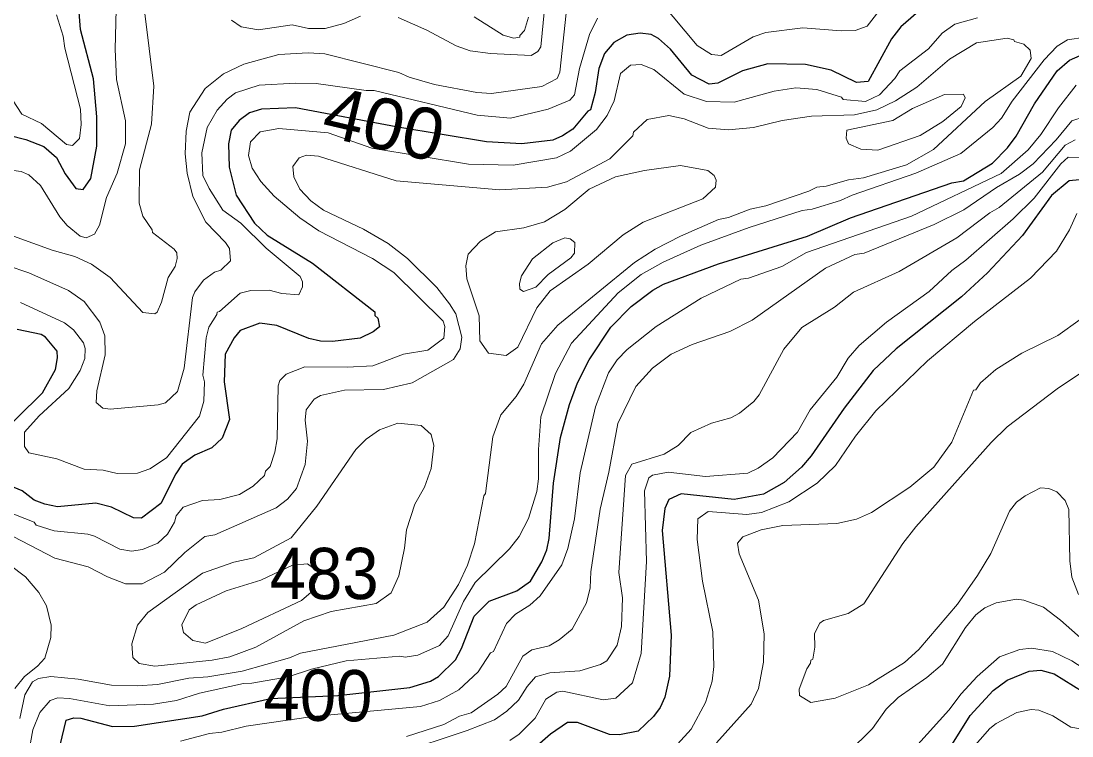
# Model space of a CAD drawing. Extents: x 673.3 to 698.5, y 6984.3 to 7012.3.
# Drawn here: x 687.231 to 688.869, y 6985.425 to 6986.54 of the extents above; entities that cross this region are included whole.
import ezdxf
from ezdxf.enums import TextEntityAlignment as Align

# ---------------------------------------------------------------- set-up
doc = ezdxf.new("R2010")
doc.units = 0
doc.header["$LTSCALE"] = 0.032
doc.layers.add('1', color=7, linetype='Continuous', lineweight=25)
doc.layers.add('2', color=7, linetype='Continuous', lineweight=13)
doc.layers.add('21', color=7, linetype='Continuous')
doc.layers.add('61', color=7, linetype='Continuous')

msp = doc.modelspace()

# ---------------------------------------------------------------- linework, layer by layer
at = {"layer": '1'}
for points in [[(687.2124, 6986.3616), (687.239, 6986.3552), (687.2669, 6986.344), (687.2869, 6986.327), (687.3004, 6986.3016), (687.3167, 6986.2786), (687.3283, 6986.2771), (687.3402, 6986.2944), (687.3494, 6986.3445), (687.3494, 6986.3905), (687.3445, 6986.4497), (687.3242, 6986.5267), (687.3184, 6986.6009)], [(688.6376, 6986.5616), (688.6025, 6986.5306), (688.5876, 6986.5122), (688.5515, 6986.4453), (688.5333, 6986.4439), (688.4936, 6986.463), (688.454, 6986.4722), (688.3951, 6986.473), (688.3557, 6986.4623), (688.3172, 6986.4431), (688.3036, 6986.4415), (688.2767, 6986.4555), (688.2433, 6986.4961), (688.2247, 6986.5127), (688.2134, 6986.5186), (688.1961, 6986.521), (688.1756, 6986.5179), (688.1554, 6986.5062), (688.1407, 6986.4894), (688.1317, 6986.4659), (688.1263, 6986.4282), (688.1188, 6986.4013), (688.1145, 6986.3992), (688.0913, 6986.3713), (688.0753, 6986.361), (688.0601, 6986.3541), (688.0116, 6986.3485), (687.9565, 6986.3517), (687.8188, 6986.3742), (687.6592, 6986.4046), (687.6059, 6986.4023), (687.5873, 6986.3965), (687.5715, 6986.3849), (687.5588, 6986.3695), (687.5546, 6986.3481), (687.5555, 6986.3119), (687.5664, 6986.2681), (687.5951, 6986.2248), (687.6151, 6986.2057), (687.6856, 6986.1623), (687.7825, 6986.0862), (687.7829, 6986.0804), (687.7876, 6986.0767), (687.7899, 6986.0629), (687.7799, 6986.0551), (687.7601, 6986.0453)], [(687.2921, 6985.4105), (687.3018, 6985.4494), (687.3137, 6985.4534), (687.3244, 6985.4527), (687.3741, 6985.4396), (687.408, 6985.4404), (687.5136, 6985.4562), (687.5468, 6985.4666), (687.6202, 6985.4833), (687.7253, 6985.4881), (687.837, 6985.5008), (687.8693, 6985.5106), (687.8817, 6985.5175), (687.9084, 6985.5437), (687.9177, 6985.5614), (687.9373, 6985.6119), (687.9608, 6985.6353), (688.0039, 6985.6512), (688.0252, 6985.6662), (688.0431, 6985.6966), (688.0507, 6985.7151), (688.0546, 6985.7328), (688.0612, 6985.8191), (688.0721, 6985.8905), (688.0859, 6985.9419), (688.0986, 6985.9754), (688.1167, 6986.0116), (688.1506, 6986.0622), (688.1823, 6986.0949), (688.2159, 6986.1204), (688.2325, 6986.1294), (688.3185, 6986.1611), (688.4567, 6986.2042), (688.5237, 6986.2328), (688.682, 6986.2875), (688.6999, 6986.2908), (688.745, 6986.3182), (688.7684, 6986.3422), (688.7821, 6986.3601), (688.8106, 6986.4106), (688.8462, 6986.4624), (688.8651, 6986.4787), (688.8819, 6986.486)], [(688.8807, 6986.292), (688.8649, 6986.2907), (688.837, 6986.2676), (688.7919, 6986.2056), (688.7377, 6986.1471), (688.697, 6986.1096), (688.5952, 6986.0289), (688.5594, 6985.9948), (688.514, 6985.936), (688.4626, 6985.8618), (688.4477, 6985.844), (688.4206, 6985.8201), (688.3882, 6985.8021), (688.3426, 6985.794), (688.2599, 6985.8027), (688.241, 6985.7935), (688.2346, 6985.7797), (688.2306, 6985.7452), (688.2445, 6985.5822), (688.242, 6985.5181), (688.2347, 6985.4855), (688.2275, 6985.4692), (688.2169, 6985.4552), (688.1931, 6985.4324), (688.1641, 6985.4266), (688.1482, 6985.4274), (688.0983, 6985.4461), (688.0827, 6985.4461), (688.0563, 6985.4279), (688.0191, 6985.395)], [(687.7601, 6986.0453), (687.7167, 6986.0399), (687.6983, 6986.0406), (687.6798, 6986.0448), (687.6299, 6986.0649), (687.6033, 6986.0688), (687.5731, 6986.0574), (687.5634, 6986.046), (687.5497, 6986.0204), (687.5481, 6985.9771), (687.5563, 6985.9185), (687.5448, 6985.8892), (687.5288, 6985.8741), (687.5021, 6985.8628), (687.4824, 6985.8486), (687.4726, 6985.834), (687.4494, 6985.7874), (687.4191, 6985.7646), (687.4064, 6985.7654), (687.3722, 6985.7816), (687.3478, 6985.7881), (687.2881, 6985.7825), (687.2683, 6985.7865), (687.2519, 6985.7929), (687.233, 6985.8072), (687.1811, 6985.8287)], [(687.1853, 6985.882), (687.2649, 6985.9602), (687.2851, 6985.9966), (687.2883, 6986.0145), (687.2875, 6986.0251), (687.2696, 6986.0471), (687.263, 6986.0508), (687.2254, 6986.0586)], [(688.3074, 6985.1771), (688.3667, 6985.1501), (688.3914, 6985.1272), (688.4008, 6985.1261), (688.4179, 6985.1335), (688.4323, 6985.1454), (688.4789, 6985.2067), (688.4958, 6985.2252), (688.5675, 6985.2822), (688.631, 6985.3546), (688.6725, 6985.3962), (688.7106, 6985.4568), (688.7463, 6985.496), (688.7683, 6985.5122), (688.8023, 6985.5259), (688.8204, 6985.5274), (688.8413, 6985.5218), (688.8864, 6985.4938)]]:
    msp.add_lwpolyline(points, dxfattribs=at)
at = {"layer": '2'}
for points in [[(688.0823, 6986.5664), (688.0709, 6986.4603), (688.0666, 6986.4501), (688.0431, 6986.4377), (687.9647, 6986.427), (687.9417, 6986.4283), (687.8757, 6986.4408), (687.8362, 6986.4522)], [(688.2287, 6986.5685), (688.2852, 6986.5018), (688.3071, 6986.4877), (688.3225, 6986.4859), (688.3721, 6986.5152), (688.3921, 6986.522), (688.4498, 6986.5292), (688.5095, 6986.5243), (688.531, 6986.525), (688.5498, 6986.5319), (688.5682, 6986.555)], [(687.1888, 6986.2154), (687.2797, 6986.1823), (687.315, 6986.1726), (687.3411, 6986.1605), (687.3704, 6986.1401), (687.4214, 6986.0855), (687.4397, 6986.0833), (687.4433, 6986.0858), (687.4505, 6986.1013), (687.4609, 6986.1398), (687.4716, 6986.1573), (687.4748, 6986.1696), (687.4741, 6986.1784), (687.47, 6986.184), (687.436, 6986.2099), (687.4356, 6986.214), (687.4213, 6986.2355), (687.4154, 6986.2556), (687.4162, 6986.3077), (687.4349, 6986.3792), (687.4381, 6986.438), (687.4236, 6986.5556)], [(687.3796, 6986.5579), (687.378, 6986.4957), (687.3804, 6986.4485), (687.3943, 6986.3841), (687.3942, 6986.3482), (687.381, 6986.3026), (687.3646, 6986.2645), (687.3535, 6986.2217), (687.3461, 6986.2076), (687.3331, 6986.2019), (687.3234, 6986.2044), (687.3034, 6986.2209), (687.2919, 6986.2347), (687.2616, 6986.2831), (687.2433, 6986.2999), (687.2318, 6986.3053), (687.2033, 6986.309)], [(687.2307, 6986.1007), (687.2992, 6986.069), (687.313, 6986.0581), (687.3286, 6986.038), (687.3314, 6986.0292), (687.3307, 6986.0135), (687.3235, 6985.9949), (687.3058, 6985.9668), (687.2598, 6985.9241), (687.237, 6985.8986), (687.2366, 6985.8763), (687.2434, 6985.8666), (687.2873, 6985.8574), (687.3297, 6985.8411), (687.3595, 6985.8394), (687.3814, 6985.8341), (687.4129, 6985.8346), (687.4323, 6985.8417), (687.4581, 6985.8586), (687.5093, 6985.9239), (687.5164, 6985.9469), (687.5171, 6985.9771), (687.5148, 6985.9878), (687.5197, 6986.0458), (687.5239, 6986.0624), (687.5367, 6986.0824), (687.5369, 6986.0861), (687.5407, 6986.0871), (687.5726, 6986.1155), (687.5894, 6986.1196), (687.6181, 6986.1204), (687.638, 6986.1147), (687.6643, 6986.1131), (687.6701, 6986.1251), (687.6702, 6986.1331), (687.6662, 6986.1416), (687.6133, 6986.1856), (687.5739, 6986.2248), (687.5458, 6986.2451), (687.5244, 6986.2787), (687.5148, 6986.2988), (687.5132, 6986.3344), (687.5216, 6986.3739), (687.5369, 6986.4008), (687.5525, 6986.4179), (687.5658, 6986.4281), (687.6025, 6986.4397), (687.6592, 6986.443), (687.6915, 6986.4422), (687.769, 6986.4314), (687.7818, 6986.4315), (687.9421, 6986.393), (687.9941, 6986.3884), (688.0528, 6986.4025), (688.0865, 6986.4162), (688.0938, 6986.4247), (688.1019, 6986.466), (688.1171, 6986.5186), (688.1297, 6986.5442)], [(687.3225, 6986.3569), (687.3249, 6986.3783), (687.3241, 6986.4025), (687.2995, 6986.4977), (687.2972, 6986.5162), (687.2866, 6986.5494)], [(687.5591, 6986.5411), (687.5745, 6986.5308), (687.6012, 6986.526), (687.654, 6986.5341), (687.6794, 6986.5283), (687.7051, 6986.5283), (687.7344, 6986.536), (687.7602, 6986.5472)], [(688.7219, 6986.5449), (688.6866, 6986.5349), (688.6669, 6986.5208), (688.6457, 6986.4966), (688.6008, 6986.4621), (688.5929, 6986.4502), (688.5691, 6986.4249), (688.5475, 6986.4145), (688.5123, 6986.4175), (688.5097, 6986.4209), (688.4714, 6986.4332), (688.4388, 6986.4355), (688.4051, 6986.4307), (688.3426, 6986.4135), (688.2993, 6986.4144), (688.2649, 6986.4257), (688.2175, 6986.4641), (688.198, 6986.4722), (688.1813, 6986.4711), (688.1654, 6986.4581), (688.1557, 6986.4155), (688.145, 6986.3925), (688.1284, 6986.3709), (688.0878, 6986.3369), (688.0658, 6986.3264), (687.9985, 6986.3151), (687.9286, 6986.3165), (687.7778, 6986.3415), (687.7102, 6986.3655), (687.6331, 6986.372), (687.6041, 6986.3669), (687.5891, 6986.3515), (687.5856, 6986.3303), (687.5916, 6986.3102), (687.6053, 6986.2896), (687.626, 6986.2666), (687.6658, 6986.2329), (687.6957, 6986.2126), (687.7792, 6986.1694), (687.8125, 6986.1477), (687.8892, 6986.0719), (687.8917, 6986.0637)], [(687.8191, 6986.5453), (687.8636, 6986.5254), (687.9092, 6986.501), (687.9315, 6986.4936), (687.9628, 6986.4894), (688.0261, 6986.4861), (688.0365, 6986.4924), (688.0414, 6986.4997), (688.0473, 6986.5585)], [(688.022, 6986.5458), (688.0159, 6986.5252), (688.0087, 6986.5175), (688.0087, 6986.5145), (687.9993, 6986.513), (687.9827, 6986.5178), (687.9377, 6986.5462)], [(687.7352, 6985.964), (687.7963, 6985.9655), (687.8411, 6985.9754), (687.9054, 6986.0121), (687.9159, 6986.0286), (687.9185, 6986.0467), (687.9087, 6986.0832), (687.8993, 6986.099), (687.8791, 6986.1241), (687.8336, 6986.1696), (687.8036, 6986.193), (687.765, 6986.2155), (687.7027, 6986.245), (687.683, 6986.2592), (687.6656, 6986.2777), (687.6566, 6986.297), (687.6549, 6986.3131), (687.6646, 6986.3264), (687.6764, 6986.3305), (687.695, 6986.3289), (687.8162, 6986.2905), (687.9775, 6986.2768), (688.052, 6986.2809), (688.0815, 6986.289), (688.1489, 6986.3247), (688.1848, 6986.3607), (688.186, 6986.3664), (688.207, 6986.3864), (688.2409, 6986.3924), (688.2648, 6986.3875), (688.302, 6986.3729), (688.3341, 6986.3704), (688.3726, 6986.3737), (688.4173, 6986.3849), (688.4633, 6986.3916), (688.5303, 6986.3937), (688.565, 6986.4014), (688.5941, 6986.4154), (688.6275, 6986.4368), (688.6783, 6986.4802), (688.7201, 6986.5056), (688.7682, 6986.5129), (688.7783, 6986.5105), (688.7797, 6986.5081), (688.7939, 6986.5038), (688.8037, 6986.4943), (688.8055, 6986.4814), (688.7893, 6986.4537), (688.7337, 6986.4143), (688.6534, 6986.3396), (688.6111, 6986.3156), (688.5442, 6986.2954), (688.5208, 6986.2923), (688.4858, 6986.2821), (688.4715, 6986.281), (688.4588, 6986.2744), (688.3921, 6986.2516), (688.3674, 6986.2466), (688.3338, 6986.2337), (688.3185, 6986.2303), (688.2589, 6986.2045), (688.2195, 6986.1841), (688.1871, 6986.1631), (688.0677, 6986.0658), (688.0426, 6986.0363), (688.0147, 6985.9738), (688.0027, 6985.9546), (687.9793, 6985.9256), (687.9668, 6985.8912), (687.9553, 6985.8031), (687.9528, 6985.7992), (687.9382, 6985.7247), (687.9272, 6985.6914), (687.9131, 6985.6614), (687.8903, 6985.6256), (687.8641, 6985.6024), (687.8123, 6985.5822), (687.6668, 6985.5543), (687.6498, 6985.5468), (687.5758, 6985.5259), (687.5227, 6985.517), (687.4927, 6985.5153), (687.4439, 6985.5052), (687.4123, 6985.5032), (687.3726, 6985.5043), (687.3204, 6985.5137), (687.2777, 6985.5177), (687.2588, 6985.5147), (687.249, 6985.5093), (687.2371, 6985.4891), (687.2296, 6985.4524)], [(687.246, 6985.4141), (687.2497, 6985.4347), (687.2608, 6985.4615), (687.2769, 6985.4803), (687.2889, 6985.4843), (687.3069, 6985.4836), (687.3696, 6985.4722), (687.438, 6985.4747), (687.4735, 6985.4804), (687.5097, 6985.4915), (687.5779, 6985.507), (687.5911, 6985.5072), (687.6475, 6985.517), (687.6839, 6985.5293), (687.7382, 6985.5421), (687.8217, 6985.5495), (687.8302, 6985.548), (687.8497, 6985.5512), (687.8836, 6985.5659), (687.897, 6985.5809), (687.921, 6985.6348), (687.939, 6985.6644), (687.9924, 6985.7169), (688.0074, 6985.7361), (688.0223, 6985.7643), (688.0351, 6985.8061), (688.0376, 6985.8259), (688.0376, 6985.8715), (688.0413, 6985.9229), (688.0644, 6985.9901), (688.089, 6986.0375), (688.1618, 6986.1159), (688.1975, 6986.1445), (688.232, 6986.1638), (688.2908, 6986.1904), (688.3658, 6986.2181), (688.4488, 6986.2442), (688.4642, 6986.2464), (688.5085, 6986.26), (688.5264, 6986.2682), (688.6259, 6986.3026), (688.6959, 6986.3334), (688.746, 6986.3736), (688.7595, 6986.3886), (688.7761, 6986.415), (688.8257, 6986.4793), (688.846, 6986.5005), (688.8621, 6986.5105), (688.8894, 6986.5146)], [(687.8362, 6986.4522), (687.8203, 6986.4594), (687.7048, 6986.4885), (687.679, 6986.4901), (687.6329, 6986.4876), (687.5786, 6986.4728), (687.5468, 6986.4577), (687.5185, 6986.4347), (687.4946, 6986.3979), (687.4887, 6986.3683), (687.487, 6986.3326), (687.4903, 6986.3026), (687.4992, 6986.2661), (687.5196, 6986.2263), (687.55, 6986.1943), (687.556, 6986.1849), (687.558, 6986.1658), (687.5426, 6986.1515), (687.5328, 6986.1481), (687.5156, 6986.1359), (687.502, 6986.1174), (687.4988, 6986.1088), (687.4855, 6985.9986), (687.475, 6985.962), (687.4564, 6985.9445), (687.4452, 6985.9412), (687.3705, 6985.9348), (687.3589, 6985.9361), (687.3486, 6985.9449), (687.3493, 6985.963), (687.3624, 6986.0194), (687.3618, 6986.0492), (687.3541, 6986.0702), (687.33, 6986.1023), (687.3054, 6986.1195), (687.2433, 6986.147), (687.2099, 6986.1584)], [(688.8754, 6986.4398), (688.8479, 6986.4045), (688.8208, 6986.3629), (688.8008, 6986.3389), (688.7589, 6986.3019), (688.6188, 6986.2355), (688.4553, 6986.179), (688.4168, 6986.1573), (688.3652, 6986.139), (688.353, 6986.1375), (688.2911, 6986.1075), (688.2211, 6986.0636), (688.176, 6986.0275), (688.1605, 6986.0113), (688.1467, 6985.9915)], [(687.2182, 6986.4171), (687.2325, 6986.3946), (687.2632, 6986.3802), (687.3022, 6986.3471), (687.3118, 6986.3455), (687.3225, 6986.3569)], [(687.8318, 6985.4242), (687.89, 6985.4428), (687.9144, 6985.4557), (687.9326, 6985.4609), (687.9746, 6985.49), (687.9876, 6985.5021), (688.0134, 6985.5497), (688.0273, 6985.5593), (688.0545, 6985.5658), (688.0701, 6985.5749), (688.0903, 6985.5916), (688.1127, 6985.6327), (688.1181, 6985.656), (688.1191, 6985.6809), (688.1337, 6985.7787), (688.1474, 6985.8365), (688.1616, 6985.9125), (688.1896, 6985.9697), (688.2152, 6985.9984), (688.2444, 6986.0202), (688.2772, 6986.0353), (688.3359, 6986.0558), (688.3709, 6986.0733), (688.4848, 6986.1545), (688.5306, 6986.1758), (688.545, 6986.1776), (688.6543, 6986.2224), (688.7008, 6986.2455), (688.7514, 6986.2804), (688.7874, 6986.3011), (688.8086, 6986.3173), (688.8444, 6986.3547), (688.8687, 6986.3843), (688.8881, 6986.3906)], [(688.874, 6986.3545), (688.8585, 6986.346), (688.8232, 6986.3043), (688.7558, 6986.2488), (688.7409, 6986.2405), (688.6896, 6986.2017), (688.5998, 6986.1494), (688.5287, 6986.1171), (688.4991, 6986.0934), (688.4483, 6986.0619), (688.4202, 6986.0281), (688.3816, 6985.9572), (688.3734, 6985.9465), (688.3512, 6985.9285), (688.3374, 6985.9212), (688.3071, 6985.9127), (688.2751, 6985.8983), (688.2555, 6985.8782), (688.2336, 6985.8645), (688.1831, 6985.849), (688.1733, 6985.8311), (688.163, 6985.68), (688.1686, 6985.6405), (688.167, 6985.5959), (688.1604, 6985.5664), (688.1441, 6985.5421), (688.1343, 6985.5365), (688.1022, 6985.5268), (688.0553, 6985.5235), (688.0333, 6985.5174), (688.0203, 6985.5021), (688.0068, 6985.4806), (687.9882, 6985.4636), (687.9691, 6985.4504), (687.9266, 6985.4333), (687.8169, 6985.3972)], [(687.9933, 6985.4179), (688.0078, 6985.4277), (688.0327, 6985.4527), (688.049, 6985.4825), (688.0663, 6985.4933), (688.0758, 6985.4949), (688.1385, 6985.4812), (688.1583, 6985.4842), (688.1844, 6985.5077), (688.1979, 6985.5536), (688.2062, 6985.6969), (688.2029, 6985.8071), (688.2097, 6985.8274), (688.2156, 6985.8315), (688.2397, 6985.8362), (688.298, 6985.8297), (688.3638, 6985.8346), (688.3799, 6985.8424), (688.4028, 6985.8586), (688.4413, 6985.8989), (688.4613, 6985.9333), (688.5029, 6985.9847), (688.5203, 6986.0143), (688.5373, 6986.0339), (688.5801, 6986.0701), (688.6467, 6986.118), (688.6817, 6986.1506), (688.7037, 6986.1667), (688.7774, 6986.2316), (688.8101, 6986.2637), (688.8519, 6986.3174), (688.863, 6986.3277), (688.8804, 6986.3264)], [(688.8766, 6986.2397), (688.8654, 6986.2143), (688.8448, 6986.181), (688.8043, 6986.1388), (688.7171, 6986.0711), (688.6439, 6986.0101), (688.5634, 6985.9321), (688.532, 6985.8927), (688.5007, 6985.8466), (688.4718, 6985.8192), (688.4279, 6985.7899), (688.3853, 6985.7734)], [(688.3153, 6985.4143), (688.369, 6985.4747), (688.3806, 6985.4988), (688.3885, 6985.54), (688.3894, 6985.5843), (688.3804, 6985.6367), (688.3506, 6985.7091), (688.3481, 6985.7255), (688.356, 6985.7356), (688.3847, 6985.7465), (688.4185, 6985.7532), (688.5026, 6985.7564), (688.5333, 6985.7629), (688.5566, 6985.7736), (688.6164, 6985.8129), (688.654, 6985.8444), (688.6818, 6985.8829), (688.7156, 6985.9644), (688.7192, 6985.965), (688.7267, 6985.9756), (688.7506, 6985.9962), (688.7907, 6986.0217), (688.8468, 6986.0494), (688.8817, 6986.0744)], [(687.8917, 6986.0637), (687.8902, 6986.0453), (687.8652, 6986.0266), (687.8275, 6986.0202), (687.7797, 6986.0024), (687.7397, 6985.9999), (687.6736, 6986.0007), (687.6443, 6985.9893), (687.6348, 6985.9791), (687.6321, 6985.9711), (687.6303, 6985.8885), (687.6271, 6985.8677), (687.6197, 6985.8452), (687.6125, 6985.8378), (687.6106, 6985.8311), (687.5932, 6985.8146), (687.5719, 6985.8017), (687.5413, 6985.7938), (687.5143, 6985.7922), (687.484, 6985.7816), (687.4732, 6985.7684), (687.4707, 6985.7583), (687.4595, 6985.7396), (687.4447, 6985.7256), (687.4206, 6985.7156), (687.4035, 6985.7133), (687.3855, 6985.7165), (687.3461, 6985.7368), (687.3354, 6985.7399), (687.2829, 6985.7449), (687.2549, 6985.7537), (687.2518, 6985.7583), (687.1638, 6985.7926)], [(688.1467, 6985.9915), (688.1268, 6985.938), (688.1027, 6985.8352), (688.0937, 6985.7635), (688.0837, 6985.7172), (688.0741, 6985.6918), (688.0405, 6985.6437), (688.0242, 6985.6289), (688.0019, 6985.6148), (687.988, 6985.6005), (687.9678, 6985.5567), (687.9632, 6985.5549), (687.9435, 6985.5248), (687.9137, 6985.4971), (687.8833, 6985.4804), (687.8539, 6985.471), (687.6859, 6985.4553), (687.5821, 6985.4404), (687.5444, 6985.4311), (687.5253, 6985.429), (687.48, 6985.4168)], [(688.8856, 6985.9927), (688.8462, 6985.9664), (688.7681, 6985.907), (688.7434, 6985.8824), (688.6256, 6985.7512), (688.6055, 6985.7252), (688.5448, 6985.631), (688.5202, 6985.6162), (688.4818, 6985.605), (688.4762, 6985.6011)], [(687.1546, 6985.7691), (687.2838, 6985.7021), (687.3362, 6985.6889), (687.366, 6985.6732), (687.3944, 6985.6621), (687.4201, 6985.6625), (687.455, 6985.6805), (687.4865, 6985.7112), (687.518, 6985.7358), (687.5336, 6985.7386), (687.6291, 6985.7805), (687.6468, 6985.7941), (687.6608, 6985.8107), (687.6743, 6985.8482), (687.6777, 6985.8849), (687.6744, 6985.9175), (687.6758, 6985.9338), (687.6884, 6985.9504), (687.6983, 6985.9559), (687.7352, 6985.964)], [(688.4762, 6985.6011), (688.4676, 6985.5846), (688.4683, 6985.5635), (688.4651, 6985.545), (688.4621, 6985.5431), (688.4618, 6985.5385), (688.4559, 6985.5295), (688.444, 6985.4982), (688.4443, 6985.4882), (688.4621, 6985.4771), (688.5003, 6985.4842), (688.552, 6985.5046), (688.6082, 6985.5396), (688.6302, 6985.5599), (688.6906, 6985.6307), (688.722, 6985.675), (688.7427, 6985.7098), (688.7718, 6985.7757), (688.7826, 6985.7894), (688.796, 6985.7997), (688.8202, 6985.8117), (688.833, 6985.811), (688.8456, 6985.8055), (688.8587, 6985.7924), (688.8641, 6985.7784), (688.8658, 6985.6983), (688.8691, 6985.6726), (688.8791, 6985.6458)], [(688.3853, 6985.7734), (688.3624, 6985.7703), (688.3023, 6985.7751), (688.286, 6985.7636), (688.2851, 6985.7312), (688.2932, 6985.6663), (688.3096, 6985.5872), (688.3111, 6985.5335), (688.3086, 6985.5107), (688.2981, 6985.477), (688.2757, 6985.4358), (688.2545, 6985.4123)], [(687.2219, 6985.4988), (687.2368, 6985.5176), (687.2572, 6985.5338), (687.2685, 6985.5462), (687.2778, 6985.5786), (687.2785, 6985.5979), (687.2708, 6985.628), (687.259, 6985.6487), (687.2381, 6985.673), (687.1871, 6985.7118)], [(688.9082, 6985.5554), (688.8514, 6985.6054), (688.8245, 6985.6256), (688.7939, 6985.6367), (688.7828, 6985.6383), (688.7507, 6985.6327), (688.7335, 6985.625), (688.7192, 6985.6138), (688.7033, 6985.5941), (688.6675, 6985.5369), (688.6428, 6985.5163), (688.5983, 6985.4848), (688.5796, 6985.4669), (688.5584, 6985.4368), (688.52, 6985.3986)], [(688.5467, 6985.3208), (688.6772, 6985.4652), (688.6962, 6985.4905), (688.7216, 6985.5177), (688.7564, 6985.5485), (688.7876, 6985.5601), (688.8059, 6985.5618), (688.8385, 6985.5569), (688.8688, 6985.5424), (688.9307, 6985.5024)], [(688.9185, 6985.4297), (688.8674, 6985.4385), (688.8395, 6985.4564), (688.8175, 6985.4655), (688.8053, 6985.4664), (688.7832, 6985.4617), (688.7507, 6985.4447), (688.7409, 6985.4368), (688.7112, 6985.4023)]]:
    msp.add_lwpolyline(points, dxfattribs=at)
for points in [[(688.6705, 6986.425), (688.7003, 6986.4257), (688.7028, 6986.4201), (688.6965, 6986.4066), (688.6679, 6986.3832), (688.6324, 6986.3611), (688.5668, 6986.3385), (688.5401, 6986.3398), (688.5207, 6986.3485), (688.5173, 6986.357), (688.5182, 6986.3695), (688.5899, 6986.3848), (688.6206, 6986.4034)], [(687.9873, 6986.0183), (688.0056, 6986.0315), (688.0354, 6986.0926), (688.0559, 6986.1193), (688.1152, 6986.1607), (688.1696, 6986.2064), (688.201, 6986.2261), (688.2939, 6986.2625), (688.3135, 6986.2808), (688.3144, 6986.2918), (688.3116, 6986.299), (688.3017, 6986.307), (688.2592, 6986.3143), (688.2032, 6986.307), (688.158, 6986.2969), (688.1166, 6986.2775), (688.0789, 6986.2457), (688.0471, 6986.2265), (688.015, 6986.2172), (687.9707, 6986.2109), (687.9475, 6986.1965), (687.9283, 6986.1761), (687.9245, 6986.1583), (687.926, 6986.1377), (687.9454, 6986.0803), (687.9464, 6986.0412), (687.9596, 6986.0219)], [(688.0146, 6986.118), (688.0089, 6986.1215), (688.0083, 6986.1307), (688.0114, 6986.1426), (688.0285, 6986.169), (688.0603, 6986.1937), (688.0786, 6986.2016), (688.087, 6986.2003), (688.0944, 6986.1944), (688.0938, 6986.178), (688.0883, 6986.1705), (688.0528, 6986.1446), (688.0335, 6986.1246)], [(687.8453, 6985.7867), (687.8603, 6985.8132), (687.8707, 6985.8422), (687.8747, 6985.8778), (687.8705, 6985.895), (687.8547, 6985.9093), (687.8184, 6985.9126), (687.7898, 6985.9024), (687.7691, 6985.8879), (687.7529, 6985.8716), (687.6924, 6985.7836), (687.6522, 6985.7342), (687.5943, 6985.7029), (687.5631, 6985.6962), (687.514, 6985.679), (687.4289, 6985.6176), (687.4131, 6985.5979), (687.404, 6985.5689), (687.4057, 6985.5472), (687.4155, 6985.5382), (687.44, 6985.5341), (687.5292, 6985.5431), (687.5569, 6985.5485), (687.5973, 6985.5635), (687.6723, 6985.6044), (687.7146, 6985.6193), (687.785, 6985.6318), (687.8081, 6985.6483), (687.8201, 6985.6745), (687.829, 6985.7179), (687.832, 6985.7464)], [(687.5756, 6985.5925), (687.6682, 6985.6362), (687.6833, 6985.6491), (687.6934, 6985.6729), (687.6934, 6985.6819), (687.6776, 6985.6936), (687.6546, 6985.6914), (687.6051, 6985.6679), (687.551, 6985.6513), (687.5041, 6985.6293), (687.4933, 6985.6217), (687.4821, 6985.5983), (687.4848, 6985.5861), (687.4991, 6985.5741), (687.5189, 6985.5699)]]:
    msp.add_lwpolyline(points, close=True, dxfattribs=at)

# ---------------------------------------------------------------- texts
at = {"layer": '21', "width": 0.95}
msp.add_text('483', height=0.08, dxfattribs=at).set_placement((687.619, 6985.6384))
at = {"layer": '61'}
for rotation, width, p in [(346.849, 1.05, (687.788, 6986.3403)), (359.17, 0.95, (687.6936, 6985.4486))]:
    msp.add_text('400', height=0.08, rotation=rotation, dxfattribs=dict(at, width=width)).set_placement(p, align=Align.CENTER)

doc.saveas('drawing.dxf')
